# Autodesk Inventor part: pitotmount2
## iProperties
Created: 2010-03
Part Number: pitotmount2
Document SubType Name: Modeling
Designer: a31883
Density: 1 g/cm^3
Author: a31883
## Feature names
1. Extrusion1
2. Extrusion2
3. Extrusion3
4. Mirror1
5. Extrusion4
6. Extrusion5
